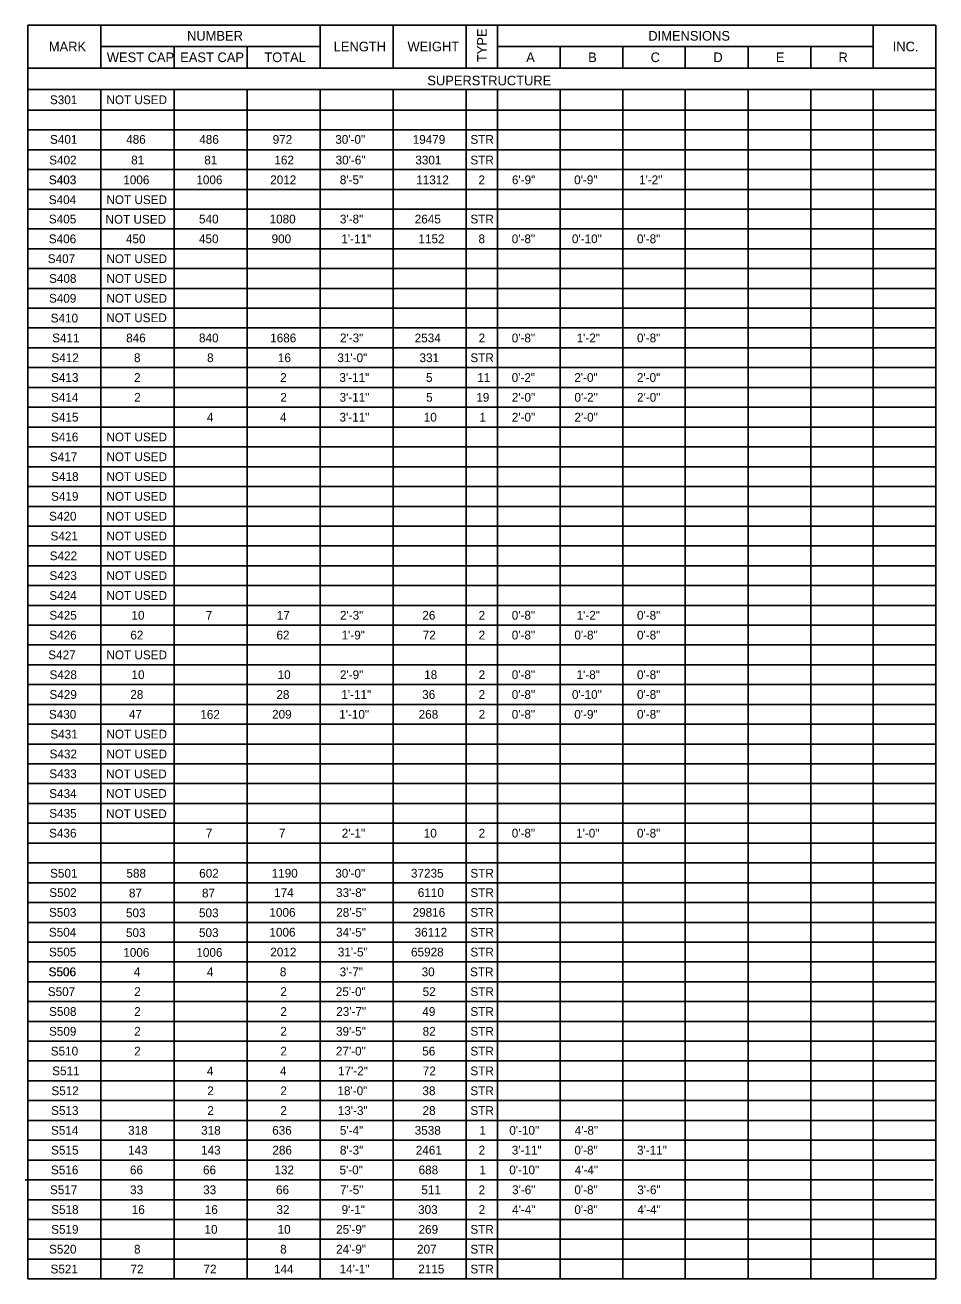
# Model space of a CAD drawing. Extents: x -47.5 to 51.5, y 0.9 to 23.7.
# Drawn here: x -47.48 to -32.93, y 0.86 to 20.88 of the extents above; entities that cross this region are included whole.
import ezdxf

# ---------------------------------------------------------------- set-up
doc = ezdxf.new("R2010")
doc.units = 0
doc.layers.add('BR_X_Slab_Const_Joint', color=7, linetype='Continuous')

msp = doc.modelspace()

# ---------------------------------------------------------------- linework, layer by layer
at = {"layer": 'BR_X_Slab_Const_Joint'}
for p, q in [((-47.433, 20.878), (-32.933, 20.878)), ((-47.433, 20.878), (-47.433, 0.863)), ((-46.267, 20.878), (-46.267, 20.193)), ((-42.767, 20.878), (-42.767, 20.193)), ((-41.6, 20.878), (-41.6, 20.193)), ((-40.433, 20.878), (-40.433, 20.193)), ((-39.933, 20.878), (-39.933, 20.193)), ((-33.933, 20.878), (-33.933, 20.193)), ((-32.933, 20.878), (-32.933, 0.863)), ((-46.267, 20.536), (-42.767, 20.536)), ((-45.1, 20.536), (-45.1, 20.193)), ((-43.933, 20.536), (-43.933, 20.193)), ((-39.933, 20.536), (-33.933, 20.536)), ((-38.933, 20.536), (-38.933, 20.193)), ((-37.931, 20.536), (-37.931, 20.193)), ((-36.936, 20.536), (-36.936, 20.193)), ((-35.933, 20.536), (-35.933, 20.193)), ((-34.933, 20.536), (-34.933, 20.193)), ((-47.433, 20.322), (-47.433, 19.057)), ((-47.433, 20.193), (-32.933, 20.193)), ((-47.433, 19.851), (-32.933, 19.851)), ((-46.267, 19.851), (-46.267, 0.863)), ((-46.155, 19.851), (-44.877, 19.851)), ((-45.1, 19.851), (-45.1, 0.863)), ((-43.933, 19.851), (-43.933, 0.863)), ((-42.767, 19.851), (-42.767, 0.863)), ((-41.6, 19.851), (-41.6, 0.863)), ((-40.433, 19.851), (-40.433, 0.863)), ((-39.933, 19.851), (-39.933, 0.863)), ((-38.933, 19.851), (-38.933, 0.863)), ((-37.931, 19.851), (-37.931, 0.863)), ((-36.936, 19.851), (-36.936, 0.863)), ((-35.933, 19.851), (-35.933, 0.863)), ((-34.933, 19.851), (-34.933, 0.863)), ((-33.933, 19.851), (-33.933, 0.863)), ((-47.433, 19.521), (-32.933, 19.521)), ((-47.433, 19.205), (-32.933, 19.205)), ((-47.433, 18.889), (-32.933, 18.889)), ((-47.433, 18.572), (-32.933, 18.572)), ((-47.433, 18.256), (-32.933, 18.256)), ((-47.433, 17.94), (-32.933, 17.94)), ((-47.433, 17.624), (-32.933, 17.624)), ((-47.433, 17.307), (-32.933, 17.307)), ((-47.433, 16.991), (-32.933, 16.991)), ((-47.433, 16.675), (-32.933, 16.675)), ((-47.433, 16.359), (-32.933, 16.359)), ((-47.433, 16.043), (-32.933, 16.043)), ((-47.433, 15.726), (-32.933, 15.726)), ((-47.433, 15.41), (-32.933, 15.41)), ((-47.433, 15.094), (-32.933, 15.094)), ((-47.433, 14.778), (-32.933, 14.778)), ((-47.433, 14.461), (-32.933, 14.461)), ((-47.433, 14.145), (-32.933, 14.145)), ((-47.433, 13.829), (-32.933, 13.829)), ((-47.433, 13.513), (-32.933, 13.513)), ((-47.433, 13.196), (-32.933, 13.196)), ((-47.433, 12.88), (-32.933, 12.88)), ((-47.433, 12.564), (-32.933, 12.564)), ((-47.433, 12.248), (-32.933, 12.248)), ((-47.433, 11.931), (-32.933, 11.931)), ((-47.433, 11.615), (-32.933, 11.615)), ((-47.433, 11.299), (-32.933, 11.299)), ((-47.433, 10.983), (-32.933, 10.983)), ((-47.433, 10.667), (-32.933, 10.667)), ((-47.433, 10.35), (-32.933, 10.35)), ((-47.433, 10.034), (-32.933, 10.034)), ((-47.433, 9.718), (-32.933, 9.718)), ((-47.433, 9.402), (-32.933, 9.402)), ((-47.433, 9.085), (-32.933, 9.085)), ((-47.433, 8.769), (-32.933, 8.769)), ((-47.433, 8.453), (-32.933, 8.453)), ((-47.433, 8.137), (-32.933, 8.137)), ((-47.433, 7.82), (-32.933, 7.82)), ((-47.433, 7.504), (-32.933, 7.504)), ((-47.433, 7.188), (-32.933, 7.188)), ((-47.433, 6.872), (-32.933, 6.872)), ((-47.433, 6.555), (-32.933, 6.555)), ((-47.433, 6.239), (-32.933, 6.239)), ((-47.433, 5.923), (-32.933, 5.923)), ((-47.433, 5.607), (-32.933, 5.607)), ((-47.433, 5.291), (-32.933, 5.291)), ((-47.433, 4.974), (-32.933, 4.974)), ((-47.433, 4.658), (-32.933, 4.658)), ((-47.433, 4.342), (-32.933, 4.342)), ((-47.433, 4.026), (-32.933, 4.026)), ((-47.433, 3.709), (-32.933, 3.709)), ((-47.433, 3.393), (-32.933, 3.393)), ((-47.433, 3.077), (-32.933, 3.077)), ((-47.433, 2.761), (-32.933, 2.761)), ((-47.479, 2.444), (-32.978, 2.444)), ((-47.433, 2.128), (-32.933, 2.128)), ((-47.433, 1.812), (-32.933, 1.812)), ((-47.433, 1.496), (-32.933, 1.496)), ((-47.433, 1.179), (-32.933, 1.179)), ((-47.433, 0.863), (-32.933, 0.863)), ((-47.433, 0.863), (-32.933, 0.863)), ((-47.433, 0.863), (-32.933, 0.863)), ((-47.433, 0.863), (-32.933, 0.863)), ((-47.433, 0.863), (-32.933, 0.863))]:
    msp.add_line(p, q, dxfattribs=at)

# ---------------------------------------------------------------- texts
msp.add_text('TYPE', height=0.154, rotation=90, dxfattribs=at).set_placement((-40.106, 20.287))
for s, height, p in [('NUMBER', 0.154, (-44.892, 20.63)), ('DIMENSIONS', 0.154, (-37.526, 20.63)), ('MARK', 0.154, (-47.099, 20.459)), ('WEST CAP', 0.154, (-46.173, 20.287)), ('EAST CAP', 0.154, (-45.001, 20.287)), ('TOTAL', 0.154, (-43.658, 20.287)), ('LENGTH', 0.154, (-42.55, 20.459)), ('WEIGHT', 0.154, (-41.371, 20.459)), ('A', 0.154, (-39.476, 20.287)), ('B', 0.154, (-38.487, 20.287)), ('C', 0.154, (-37.489, 20.287)), ('D', 0.154, (-36.487, 20.287)), ('E', 0.154, (-35.489, 20.287)), ('R', 0.154, (-34.489, 20.287)), ('INC.', 0.154, (-33.623, 20.459)), ('SUPERSTRUCTURE', 0.154, (-41.055, 19.916)), ('S301', 0.14, (-47.081, 19.616)), ('NOT USED', 0.14, (-46.179, 19.616)), ('S401', 0.14, (-47.08, 18.983)), ('486', 0.14, (-45.864, 18.983)), ('486', 0.14, (-44.697, 18.983)), ('972', 0.14, (-43.524, 18.983)), ('30\'-0"', 0.14, (-42.525, 18.983)), ('19479', 0.14, (-41.289, 18.983)), ('STR', 0.14, (-40.367, 18.983)), ('S402', 0.14, (-47.093, 18.654)), ('S402', 0.14, (-47.093, 18.654)), ('81', 0.14, (-45.784, 18.654)), ('81', 0.14, (-44.617, 18.654)), ('162', 0.14, (-43.497, 18.654)), ('30\'-6"', 0.14, (-42.519, 18.654)), ('3301', 0.14, (-41.247, 18.654)), ('STR', 0.14, (-40.367, 18.654)), ('S403', 0.14, (-47.099, 18.338)), ('S403', 0.14, (-47.096, 18.338)), ('1006', 0.14, (-45.91, 18.338)), ('1006', 0.14, (-44.743, 18.338)), ('2012', 0.14, (-43.564, 18.338)), ('8\'-5"', 0.14, (-42.452, 18.338)), ('11312', 0.14, (-41.232, 18.338)), ('2', 0.14, (-40.238, 18.338)), ('6\'-9"', 0.14, (-39.704, 18.338)), ('0\'-9"', 0.14, (-38.71, 18.338)), ('1\'-2"', 0.14, (-37.674, 18.338)), ('S404', 0.14, (-47.099, 18.021)), ('S404', 0.14, (-47.099, 18.021)), ('NOT USED', 0.14, (-46.179, 18.021)), ('S405', 0.14, (-47.098, 17.712)), ('S405', 0.14, (-47.098, 17.712)), ('NOT USED', 0.14, (-46.194, 17.708)), ('540', 0.14, (-44.701, 17.712)), ('1080', 0.14, (-43.574, 17.712)), ('3\'-8"', 0.14, (-42.451, 17.712)), ('2645', 0.14, (-41.256, 17.712)), ('STR', 0.14, (-40.367, 17.712)), ('S406', 0.14, (-47.099, 17.396)), ('450', 0.14, (-45.868, 17.396)), ('450', 0.14, (-44.701, 17.396)), ('900', 0.14, (-43.542, 17.396)), ('1\'-11"', 0.14, (-42.428, 17.396)), ('1152', 0.14, (-41.196, 17.396)), ('8', 0.14, (-40.238, 17.396)), ('0\'-8"', 0.14, (-39.707, 17.396)), ('0\'-10"', 0.14, (-38.746, 17.396)), ('0\'-8"', 0.14, (-37.707, 17.396)), ('S407', 0.14, (-47.116, 17.079)), ('NOT USED', 0.14, (-46.179, 17.079)), ('S408', 0.14, (-47.095, 16.763)), ('NOT USED', 0.14, (-46.179, 16.763)), ('S409', 0.14, (-47.097, 16.447)), ('NOT USED', 0.14, (-46.179, 16.447)), ('S410', 0.14, (-47.069, 16.131)), ('NOT USED', 0.14, (-46.182, 16.136)), ('S411', 0.14, (-47.046, 15.814)), ('846', 0.14, (-45.864, 15.814)), ('840', 0.14, (-44.701, 15.814)), ('1686', 0.14, (-43.564, 15.814)), ('2\'-3"', 0.14, (-42.45, 15.814)), ('2534', 0.14, (-41.257, 15.814)), ('2', 0.14, (-40.236, 15.814)), ('0\'-8"', 0.14, (-39.707, 15.814)), ('1\'-2"', 0.14, (-38.671, 15.814)), ('0\'-8"', 0.14, (-37.707, 15.814)), ('S412', 0.14, (-47.058, 15.498)), ('8', 0.14, (-45.739, 15.498)), ('8', 0.14, (-44.572, 15.498)), ('16', 0.14, (-43.442, 15.498)), ('31\'-0"', 0.14, (-42.491, 15.498)), ('331', 0.14, (-41.18, 15.498)), ('STR', 0.14, (-40.367, 15.498)), ('S413', 0.14, (-47.064, 15.182)), ('S413', 0.14, (-47.062, 15.182)), ('S413', 0.14, (-47.062, 15.182)), ('2', 0.14, (-45.738, 15.182)), ('2', 0.14, (-43.405, 15.182)), ('3\'-11"', 0.14, (-42.459, 15.182)), ('5', 0.14, (-41.076, 15.182)), ('11', 0.14, (-40.258, 15.182)), ('0\'-2"', 0.14, (-39.708, 15.182)), ('2\'-0"', 0.14, (-38.708, 15.182)), ('2\'-0"', 0.14, (-37.708, 15.182)), ('S414', 0.14, (-47.064, 14.866)), ('2', 0.14, (-45.736, 14.866)), ('2', 0.14, (-43.402, 14.866)), ('3\'-11"', 0.14, (-42.457, 14.866)), ('5', 0.14, (-41.074, 14.866)), ('19', 0.14, (-40.273, 14.866)), ('2\'-0"', 0.14, (-39.706, 14.866)), ('0\'-2"', 0.14, (-38.706, 14.866)), ('2\'-0"', 0.14, (-37.706, 14.866)), ('S415', 0.14, (-47.063, 14.549)), ('4', 0.14, (-44.575, 14.549)), ('4', 0.14, (-43.408, 14.549)), ('3\'-11"', 0.14, (-42.457, 14.549)), ('10', 0.14, (-41.112, 14.549)), ('1', 0.14, (-40.223, 14.549)), ('2\'-0"', 0.14, (-39.706, 14.549)), ('2\'-0"', 0.14, (-38.706, 14.549)), ('S416', 0.14, (-47.065, 14.233)), ('NOT USED', 0.14, (-46.179, 14.233)), ('S417', 0.14, (-47.082, 13.917)), ('NOT USED', 0.14, (-46.179, 13.917)), ('S418', 0.14, (-47.061, 13.601)), ('NOT USED', 0.14, (-46.179, 13.601)), ('S419', 0.14, (-47.063, 13.285)), ('NOT USED', 0.14, (-46.179, 13.285)), ('S420', 0.14, (-47.095, 12.968)), ('NOT USED', 0.14, (-46.179, 12.968)), ('S421', 0.14, (-47.072, 12.652)), ('NOT USED', 0.14, (-46.179, 12.652)), ('S422', 0.14, (-47.085, 12.336)), ('NOT USED', 0.14, (-46.179, 12.336)), ('S423', 0.14, (-47.089, 12.02)), ('NOT USED', 0.14, (-46.179, 12.02)), ('S424', 0.14, (-47.091, 11.703)), ('NOT USED', 0.14, (-46.179, 11.703)), ('S425', 0.14, (-47.09, 11.387)), ('10', 0.14, (-45.779, 11.387)), ('7', 0.14, (-44.592, 11.387)), ('17', 0.14, (-43.459, 11.387)), ('2\'-3"', 0.14, (-42.45, 11.387)), ('26', 0.14, (-41.135, 11.387)), ('2', 0.14, (-40.236, 11.387)), ('0\'-8"', 0.14, (-39.707, 11.387)), ('1\'-2"', 0.14, (-38.671, 11.387)), ('0\'-8"', 0.14, (-37.707, 11.387)), ('S426', 0.14, (-47.091, 11.071)), ('62', 0.14, (-45.797, 11.071)), ('62', 0.14, (-43.464, 11.071)), ('1\'-9"', 0.14, (-42.424, 11.071)), ('72', 0.14, (-41.128, 11.071)), ('2', 0.14, (-40.236, 11.071)), ('0\'-8"', 0.14, (-39.707, 11.071)), ('0\'-8"', 0.14, (-38.707, 11.071)), ('0\'-8"', 0.14, (-37.707, 11.071)), ('S427', 0.14, (-47.108, 10.755)), ('NOT USED', 0.14, (-46.179, 10.755)), ('S428', 0.14, (-47.088, 10.438)), ('10', 0.14, (-45.779, 10.438)), ('10', 0.14, (-43.446, 10.438)), ('2\'-9"', 0.14, (-42.45, 10.438)), ('18', 0.14, (-41.105, 10.438)), ('2', 0.14, (-40.236, 10.438)), ('0\'-8"', 0.14, (-39.707, 10.438)), ('1\'-8"', 0.14, (-38.672, 10.438)), ('0\'-8"', 0.14, (-37.707, 10.438)), ('S429', 0.14, (-47.089, 10.122)), ('28', 0.14, (-45.798, 10.122)), ('28', 0.14, (-43.465, 10.122)), ('1\'-11"', 0.14, (-42.428, 10.122)), ('36', 0.14, (-41.137, 10.122)), ('2', 0.14, (-40.236, 10.122)), ('0\'-8"', 0.14, (-39.707, 10.122)), ('0\'-10"', 0.14, (-38.746, 10.122)), ('0\'-8"', 0.14, (-37.707, 10.122)), ('S430', 0.14, (-47.098, 9.806)), ('47', 0.14, (-45.82, 9.806)), ('162', 0.14, (-44.68, 9.804)), ('209', 0.14, (-43.534, 9.806)), ('1\'-10"', 0.14, (-42.462, 9.806)), ('268', 0.14, (-41.193, 9.806)), ('2', 0.14, (-40.236, 9.806)), ('0\'-8"', 0.14, (-39.707, 9.806)), ('0\'-9"', 0.14, (-38.708, 9.806)), ('0\'-8"', 0.14, (-37.707, 9.806)), ('S431', 0.14, (-47.074, 9.49)), ('NOT USED', 0.14, (-46.179, 9.49)), ('S432', 0.14, (-47.087, 9.173)), ('NOT USED', 0.14, (-46.179, 9.173)), ('S433', 0.14, (-47.091, 8.857)), ('NOT USED', 0.14, (-46.184, 8.855)), ('S434', 0.14, (-47.093, 8.541)), ('NOT USED', 0.14, (-46.184, 8.542)), ('S435', 0.14, (-47.092, 8.225)), ('NOT USED', 0.14, (-46.183, 8.219)), ('S436', 0.14, (-47.094, 7.909)), ('7', 0.14, (-44.592, 7.909)), ('7', 0.14, (-43.425, 7.909)), ('2\'-1"', 0.14, (-42.421, 7.909)), ('10', 0.14, (-41.112, 7.909)), ('2', 0.14, (-40.236, 7.909)), ('0\'-8"', 0.14, (-39.707, 7.909)), ('1\'-0"', 0.14, (-38.679, 7.909)), ('0\'-8"', 0.14, (-37.707, 7.909)), ('S501', 0.14, (-47.079, 7.269)), ('588', 0.14, (-45.86, 7.269)), ('602', 0.14, (-44.698, 7.269)), ('1190', 0.14, (-43.541, 7.269)), ('30\'-0"', 0.14, (-42.525, 7.269)), ('37235', 0.14, (-41.316, 7.269)), ('STR', 0.14, (-40.367, 7.269)), ('S502', 0.14, (-47.092, 6.96)), ('S502', 0.14, (-47.092, 6.96)), ('87', 0.14, (-45.82, 6.953)), ('87', 0.14, (-44.653, 6.953)), ('174', 0.14, (-43.501, 6.96)), ('33\'-8"', 0.14, (-42.513, 6.96)), ('6110', 0.14, (-41.207, 6.96)), ('STR', 0.14, (-40.367, 6.96)), ('S503', 0.14, (-47.096, 6.644)), ('S503', 0.14, (-47.096, 6.644)), ('503', 0.14, (-45.867, 6.637)), ('503', 0.14, (-44.701, 6.637)), ('1006', 0.14, (-43.576, 6.644)), ('28\'-5"', 0.14, (-42.51, 6.644)), ('29816', 0.14, (-41.29, 6.644)), ('STR', 0.14, (-40.367, 6.644)), ('S504', 0.14, (-47.098, 6.327)), ('S504', 0.14, (-47.098, 6.327)), ('503', 0.14, (-45.867, 6.321)), ('503', 0.14, (-44.701, 6.321)), ('1006', 0.14, (-43.576, 6.327)), ('34\'-5"', 0.14, (-42.512, 6.327)), ('36112', 0.14, (-41.258, 6.327)), ('STR', 0.14, (-40.367, 6.327)), ('S505', 0.14, (-47.097, 6.011)), ('S505', 0.14, (-47.097, 6.011)), ('1006', 0.14, (-45.91, 6.005)), ('1006', 0.14, (-44.743, 6.005)), ('2012', 0.14, (-43.562, 6.011)), ('31\'-5"', 0.14, (-42.484, 6.011)), ('65928', 0.14, (-41.315, 6.011)), ('STR', 0.14, (-40.367, 6.011)), ('S506', 0.14, (-47.104, 5.695)), ('S506', 0.14, (-47.099, 5.695)), ('4', 0.14, (-45.742, 5.695)), ('4', 0.14, (-44.575, 5.695)), ('8', 0.14, (-43.41, 5.695)), ('3\'-7"', 0.14, (-42.455, 5.695)), ('30', 0.14, (-41.146, 5.695)), ('STR', 0.14, (-40.372, 5.695)), ('S507', 0.14, (-47.115, 5.379)), ('2', 0.14, (-45.736, 5.379)), ('2', 0.14, (-43.402, 5.379)), ('25\'-0"', 0.14, (-42.516, 5.379)), ('52', 0.14, (-41.13, 5.379)), ('STR', 0.14, (-40.367, 5.379)), ('S508', 0.14, (-47.095, 5.062)), ('2', 0.14, (-45.736, 5.062)), ('2', 0.14, (-43.402, 5.062)), ('23\'-7"', 0.14, (-42.51, 5.062)), ('49', 0.14, (-41.135, 5.062)), ('STR', 0.14, (-40.367, 5.062)), ('S509', 0.14, (-47.096, 4.746)), ('2', 0.14, (-45.736, 4.746)), ('2', 0.14, (-43.402, 4.746)), ('39\'-5"', 0.14, (-42.513, 4.746)), ('82', 0.14, (-41.13, 4.746)), ('STR', 0.14, (-40.367, 4.746)), ('S510', 0.14, (-47.068, 4.43)), ('2', 0.14, (-45.736, 4.43)), ('2', 0.14, (-43.402, 4.43)), ('27\'-0"', 0.14, (-42.515, 4.43)), ('56', 0.14, (-41.136, 4.43)), ('STR', 0.14, (-40.367, 4.43)), ('S511', 0.14, (-47.045, 4.114)), ('4', 0.14, (-44.575, 4.114)), ('4', 0.14, (-43.408, 4.114)), ('17\'-2"', 0.14, (-42.481, 4.114)), ('72', 0.14, (-41.128, 4.114)), ('STR', 0.14, (-40.367, 4.114)), ('S512', 0.14, (-47.058, 3.797)), ('2', 0.14, (-44.569, 3.797)), ('2', 0.14, (-43.402, 3.797)), ('18\'-0"', 0.14, (-42.49, 3.797)), ('38', 0.14, (-41.133, 3.797)), ('STR', 0.14, (-40.367, 3.797)), ('S513', 0.14, (-47.062, 3.481)), ('2', 0.14, (-44.569, 3.481)), ('2', 0.14, (-43.402, 3.481)), ('13\'-3"', 0.14, (-42.485, 3.481)), ('28', 0.14, (-41.131, 3.481)), ('STR', 0.14, (-40.367, 3.481)), ('S514', 0.14, (-47.064, 3.165)), ('318', 0.14, (-45.833, 3.165)), ('318', 0.14, (-44.667, 3.165)), ('636', 0.14, (-43.532, 3.165)), ('5\'-4"', 0.14, (-42.451, 3.165)), ('3538', 0.14, (-41.256, 3.165)), ('1', 0.14, (-40.223, 3.165)), ('0\'-10"', 0.14, (-39.746, 3.165)), ('4\'-8"', 0.14, (-38.701, 3.165)), ('S515', 0.14, (-47.063, 2.849)), ('143', 0.14, (-45.834, 2.849)), ('143', 0.14, (-44.667, 2.849)), ('286', 0.14, (-43.529, 2.849)), ('8\'-3"', 0.14, (-42.451, 2.849)), ('2461', 0.14, (-41.239, 2.849)), ('2', 0.14, (-40.236, 2.849)), ('3\'-11"', 0.14, (-39.707, 2.849)), ('0\'-8"', 0.14, (-38.707, 2.849)), ('3\'-11"', 0.14, (-37.707, 2.849)), ('S516', 0.14, (-47.064, 2.533)), ('66', 0.14, (-45.804, 2.533)), ('66', 0.14, (-44.637, 2.533)), ('132', 0.14, (-43.497, 2.533)), ('5\'-0"', 0.14, (-42.457, 2.533)), ('688', 0.14, (-41.194, 2.533)), ('1', 0.14, (-40.223, 2.533)), ('0\'-10"', 0.14, (-39.746, 2.533)), ('4\'-4"', 0.14, (-38.701, 2.533)), ('S517', 0.14, (-47.081, 2.216)), ('33', 0.14, (-45.801, 2.216)), ('33', 0.14, (-44.635, 2.216)), ('66', 0.14, (-43.471, 2.216)), ('7\'-5"', 0.14, (-42.449, 2.216)), ('511', 0.14, (-41.15, 2.216)), ('2', 0.14, (-40.236, 2.216)), ('3\'-6"', 0.14, (-39.702, 2.216)), ('0\'-8"', 0.14, (-38.707, 2.216)), ('3\'-6"', 0.14, (-37.702, 2.216)), ('S518', 0.14, (-47.061, 1.9)), ('16', 0.14, (-45.775, 1.9)), ('16', 0.14, (-44.609, 1.9)), ('32', 0.14, (-43.464, 1.9)), ('9\'-1"', 0.14, (-42.424, 1.9)), ('303', 0.14, (-41.202, 1.9)), ('2', 0.14, (-40.236, 1.9)), ('4\'-4"', 0.14, (-39.701, 1.9)), ('0\'-8"', 0.14, (-38.707, 1.9)), ('4\'-4"', 0.14, (-37.701, 1.9)), ('S519', 0.14, (-47.062, 1.584)), ('10', 0.14, (-44.613, 1.584)), ('10', 0.14, (-43.446, 1.584)), ('25\'-9"', 0.14, (-42.511, 1.584)), ('269', 0.14, (-41.195, 1.584)), ('STR', 0.14, (-40.367, 1.584)), ('S520', 0.14, (-47.095, 1.268)), ('8', 0.14, (-45.739, 1.268)), ('8', 0.14, (-43.405, 1.268)), ('24\'-9"', 0.14, (-42.511, 1.268)), ('207', 0.14, (-41.219, 1.268)), ('STR', 0.14, (-40.367, 1.268)), ('S521', 0.14, (-47.072, 0.951)), ('72', 0.14, (-45.795, 0.951)), ('72', 0.14, (-44.629, 0.951)), ('144', 0.14, (-43.503, 0.951)), ('14\'-1"', 0.14, (-42.456, 0.951)), ('2115', 0.14, (-41.199, 0.951)), ('STR', 0.14, (-40.367, 0.951))]:
    msp.add_text(s, height=height, dxfattribs=at).set_placement(p)

doc.saveas('drawing.dxf')
